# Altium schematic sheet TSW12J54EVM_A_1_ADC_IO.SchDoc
size 431 x 279 mm; Date: Not shown in title block; ApprovedBy: Not shown in title block; CheckedBy: Not shown in title block; Author: Not shown in title block; CompanyName: Not shown in title block; Engineer: Not shown in title block; Organization: Not shown in title block; Address1: Not shown in title block; Address2: Not shown in title block; Address3: Not shown in title block; Address4: Not shown in title block; DocumentNumber: 1; Revision: Use project parameter SCH_Rev; SheetNumber: 1; SheetTotal: 8; PageSetup: Record=PageOptions¦CenterHorizontal=True¦CenterVertical=True¦PrintScale=1.32¦XCorrection=1.00¦YCorrection=1.00¦PrintKind=0¦BorderSize=5000000¦LeftOffset=0¦BottomOffset=0¦Orientation=2¦PaperLength=1000¦PaperWidth=1000¦Scale=100¦PaperSource=15¦PrintQuality=600¦MediaType=1¦DitherType=10¦PaperKind=Letter¦PrintScaleMode=1
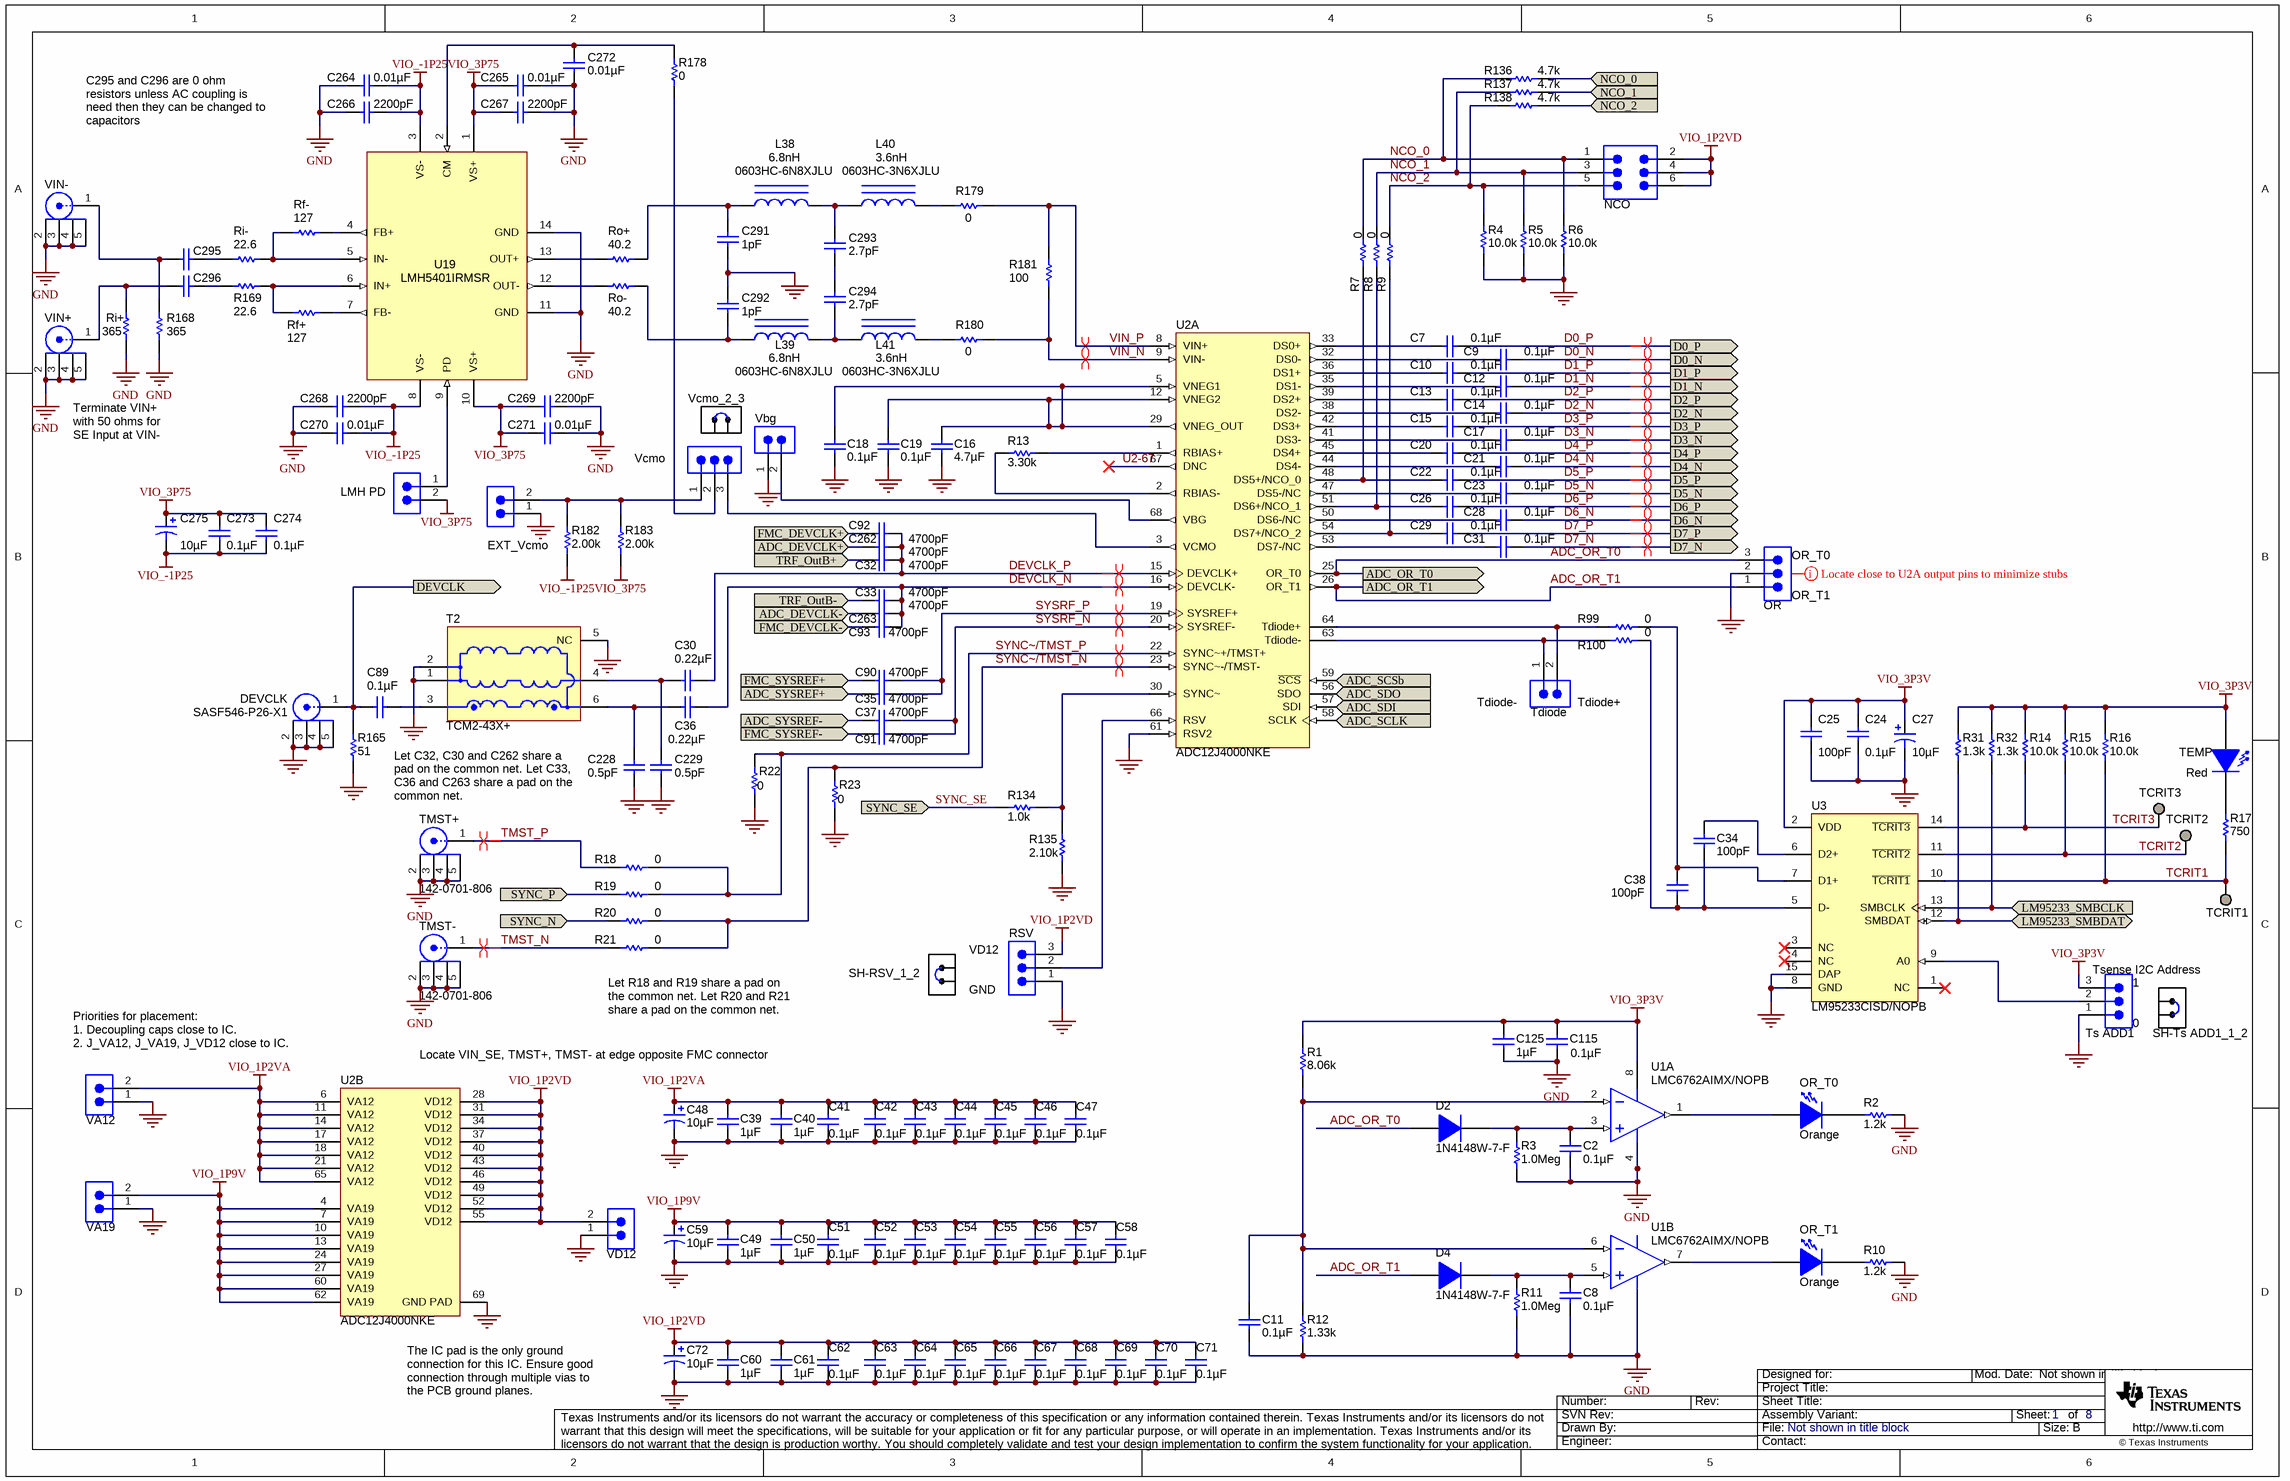
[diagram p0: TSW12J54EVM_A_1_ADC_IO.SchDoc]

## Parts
C2  ValueDisplayed: 0.1µF  [0402L]  (hidden comment: GRM155R71A104KA01D)
C7  ValueDisplayed: 0.1µF  [0201]  (hidden comment: C0603X5R0J104K)
C8  ValueDisplayed: 0.1µF  [0402L]  (hidden comment: GRM155R71A104KA01D)
C9  ValueDisplayed: 0.1µF  [0201]  (hidden comment: C0603X5R0J104K)
C10  ValueDisplayed: 0.1µF  [0201]  (hidden comment: C0603X5R0J104K)
C11  ValueDisplayed: 0.1µF  [0402L]  (hidden comment: GRM155R71A104KA01D)
C12  ValueDisplayed: 0.1µF  [0201]  (hidden comment: C0603X5R0J104K)
C13  ValueDisplayed: 0.1µF  [0201]  (hidden comment: C0603X5R0J104K)
C14  ValueDisplayed: 0.1µF  [0201]  (hidden comment: C0603X5R0J104K)
C15  ValueDisplayed: 0.1µF  [0201]  (hidden comment: C0603X5R0J104K)
C16  ValueDisplayed: 4.7µF  [0402L]  (hidden comment: C1005X5R0J475M050BC)
C17  ValueDisplayed: 0.1µF  [0201]  (hidden comment: C0603X5R0J104K)
C18  ValueDisplayed: 0.1µF  [0402L]  (hidden comment: C1005X5R1A104K)
C19  ValueDisplayed: 0.1µF  [0402L]  (hidden comment: C1005X5R1A104K)
C20  ValueDisplayed: 0.1µF  [0201]  (hidden comment: C0603X5R0J104K)
C21  ValueDisplayed: 0.1µF  [0201]  (hidden comment: C0603X5R0J104K)
C22  ValueDisplayed: 0.1µF  [0201]  (hidden comment: C0603X5R0J104K)
C23  ValueDisplayed: 0.1µF  [0201]  (hidden comment: C0603X5R0J104K)
C24  ValueDisplayed: 0.1µF  [0603L]  (hidden comment: 0603YC104JAT2A)
C25  ValueDisplayed: 100pF  [0603L]  (hidden comment: 06035A101JAT2A)
C26  ValueDisplayed: 0.1µF  [0201]  (hidden comment: C0603X5R0J104K)
C27  ValueDisplayed: 10µF  [3528-21]  (hidden comment: 293D106X0010B2TE3)
C28  ValueDisplayed: 0.1µF  [0201]  (hidden comment: C0603X5R0J104K)
C29  ValueDisplayed: 0.1µF  [0201]  (hidden comment: C0603X5R0J104K)
C30  ValueDisplayed: 0.22µF  [0201]  (hidden comment: C0603X5R0J224M)
C31  ValueDisplayed: 0.1µF  [0201]  (hidden comment: C0603X5R0J104K)
C32  ValueDisplayed: 4700pF  [0201]  (hidden comment: GRM033R61A472KA01D)
C33  ValueDisplayed: 4700pF  [0201]  (hidden comment: GRM033R61A472KA01D)
C34  ValueDisplayed: 100pF  [0603L]  (hidden comment: 06035A101JAT2A)
C35  ValueDisplayed: 4700pF  [0201]  (hidden comment: GRM033R61A472KA01D)
C36  ValueDisplayed: 0.22µF  [0201]  (hidden comment: C0603X5R0J224M)
C37  ValueDisplayed: 4700pF  [0201]  (hidden comment: GRM033R61A472KA01D)
C38  ValueDisplayed: 100pF  [0603L]  (hidden comment: 06035A101JAT2A)
C39  ValueDisplayed: 1µF  [0603L]  (hidden comment: C1608X5R1A105K)
C40  ValueDisplayed: 1µF  [0603L]  (hidden comment: C1608X5R1A105K)
C41  ValueDisplayed: 0.1µF  [0201]  (hidden comment: C0603X5R0J104K)
C42  ValueDisplayed: 0.1µF  [0201]  (hidden comment: C0603X5R0J104K)
C43  ValueDisplayed: 0.1µF  [0201]  (hidden comment: C0603X5R0J104K)
C44  ValueDisplayed: 0.1µF  [0201]  (hidden comment: C0603X5R0J104K)
C45  ValueDisplayed: 0.1µF  [0201]  (hidden comment: C0603X5R0J104K)
C46  ValueDisplayed: 0.1µF  [0201]  (hidden comment: C0603X5R0J104K)
C47  ValueDisplayed: 0.1µF  [0201]  (hidden comment: C0603X5R0J104K)
C48  ValueDisplayed: 10µF  [3528-21]  (hidden comment: 293D106X0010B2TE3)
C49  ValueDisplayed: 1µF  [0603L]  (hidden comment: C1608X5R1A105K)
C50  ValueDisplayed: 1µF  [0603L]  (hidden comment: C1608X5R1A105K)
C51  ValueDisplayed: 0.1µF  [0201]  (hidden comment: C0603X5R0J104K)
C52  ValueDisplayed: 0.1µF  [0201]  (hidden comment: C0603X5R0J104K)
C53  ValueDisplayed: 0.1µF  [0201]  (hidden comment: C0603X5R0J104K)
C54  ValueDisplayed: 0.1µF  [0201]  (hidden comment: C0603X5R0J104K)
C55  ValueDisplayed: 0.1µF  [0201]  (hidden comment: C0603X5R0J104K)
C56  ValueDisplayed: 0.1µF  [0201]  (hidden comment: C0603X5R0J104K)
C57  ValueDisplayed: 0.1µF  [0201]  (hidden comment: C0603X5R0J104K)
C58  ValueDisplayed: 0.1µF  [0201]  (hidden comment: C0603X5R0J104K)
C59  ValueDisplayed: 10µF  [3528-21]  (hidden comment: 293D106X0010B2TE3)
C60  ValueDisplayed: 1µF  [0603L]  (hidden comment: C1608X5R1A105K)
C61  ValueDisplayed: 1µF  [0603L]  (hidden comment: C1608X5R1A105K)
C62  ValueDisplayed: 0.1µF  [0201]  (hidden comment: C0603X5R0J104K)
C63  ValueDisplayed: 0.1µF  [0201]  (hidden comment: C0603X5R0J104K)
C64  ValueDisplayed: 0.1µF  [0201]  (hidden comment: C0603X5R0J104K)
C65  ValueDisplayed: 0.1µF  [0201]  (hidden comment: C0603X5R0J104K)
C66  ValueDisplayed: 0.1µF  [0201]  (hidden comment: C0603X5R0J104K)
C67  ValueDisplayed: 0.1µF  [0201]  (hidden comment: C0603X5R0J104K)
C68  ValueDisplayed: 0.1µF  [0201]  (hidden comment: C0603X5R0J104K)
C69  ValueDisplayed: 0.1µF  [0201]  (hidden comment: C0603X5R0J104K)
C70  ValueDisplayed: 0.1µF  [0201]  (hidden comment: C0603X5R0J104K)
C71  ValueDisplayed: 0.1µF  [0201]  (hidden comment: C0603X5R0J104K)
C72  ValueDisplayed: 10µF  [3528-21]  (hidden comment: 293D106X0010B2TE3)
C89  ValueDisplayed: 0.1µF  [0402L]  (hidden comment: C1005X5R1A104K)
C90  ValueDisplayed: 4700pF  [0201]  (hidden comment: GRM033R61A472KA01D)
C91  ValueDisplayed: 4700pF  [0201]  (hidden comment: GRM033R61A472KA01D)
C92  ValueDisplayed: 4700pF  [0201]  (hidden comment: GRM033R61A472KA01D)
C93  ValueDisplayed: 4700pF  [0201]  (hidden comment: GRM033R61A472KA01D)
C115  ValueDisplayed: 0.1µF  [0603L]  (hidden comment: 0603YC104JAT2A)
C125  ValueDisplayed: 1µF  [0603L]  (hidden comment: C1608X5R1A105K)
C228  ValueDisplayed: 0.5pF  [0402L]  (hidden comment: 500R07S0R5BV4T)
C229  ValueDisplayed: 0.5pF  [0402L]  (hidden comment: 500R07S0R5BV4T)
C262  ValueDisplayed: 4700pF  [0201]  (hidden comment: GRM033R61A472KA01D)
C263  ValueDisplayed: 4700pF  [0201]  (hidden comment: GRM033R61A472KA01D)
C264  ValueDisplayed: 0.01µF  [0306]  (hidden comment: LLL185R71E103MA01L)
C265  ValueDisplayed: 0.01µF  [0306]  (hidden comment: LLL185R71E103MA01L)
C266  ValueDisplayed: 2200pF  [0306]  (hidden comment: LLL185R71H222MA01L)
C267  ValueDisplayed: 2200pF  [0306]  (hidden comment: LLL185R71H222MA01L)
C268  ValueDisplayed: 2200pF  [0306]  (hidden comment: LLL185R71H222MA01L)
C269  ValueDisplayed: 2200pF  [0306]  (hidden comment: LLL185R71H222MA01L)
C270  ValueDisplayed: 0.01µF  [0306]  (hidden comment: LLL185R71E103MA01L)
C271  ValueDisplayed: 0.01µF  [0306]  (hidden comment: LLL185R71E103MA01L)
C272  ValueDisplayed: 0.01µF  [0402L]  (hidden comment: C1005X7R1E103K)
C273  ValueDisplayed: 0.1µF  [0402L]  (hidden comment: C1005X5R1A104K)
C274  ValueDisplayed: 0.1µF  [0402L]  (hidden comment: C1005X5R1A104K)
C275  ValueDisplayed: 10µF  [3216-18]  (hidden comment: TPSA106K010R0900)
C291  ValueDisplayed: 1pF  [0402L]  (hidden comment: GRM1555C1H1R0CA01D)
C292  ValueDisplayed: 1pF  [0402L]  (hidden comment: GRM1555C1H1R0CA01D)
C293  ValueDisplayed: 2.7pF  [0402L]  (hidden comment: GRM1555C1H2R7CA01D)
C294  ValueDisplayed: 2.7pF  [0402L]  (hidden comment: GRM1555C1H2R7CA01D)
C295  Used in BOM report  [0402L]  (value not drawn)
C296  Used in BOM report  [0402L]  (value not drawn)
D2  1N4148W-7-F  [SOD-123]
D4  1N4148W-7-F  [SOD-123]
DEVCLK  SASF546-P26-X1  [CONN_LTI_SASF546-P26-X1]
EXT_Vcmo  TSW-102-07-G-S  [TSW-102-07-G-S]  (value not drawn)
L38  0603HC-6N8XJLU  ValueDisplayed: 6.8nH  [0603HC]
L39  0603HC-6N8XJLU  ValueDisplayed: 6.8nH  [0603HC]
L40  0603HC-3N6XJLU  ValueDisplayed: 3.6nH  [0603HC]
L41  0603HC-3N6XJLU  ValueDisplayed: 3.6nH  [0603HC]
LMH_PD  TSW-102-07-G-S  [TSW-102-07-G-S]  (value not drawn)
NCO  TSW-103-07-G-D  [TSW-103-07-G-D]  (value not drawn)
OR  TSW-103-07-G-S  [TSW-103-07-G-S]  (value not drawn)
OR_T0  value Orange  [LED_LTST-C190]  (hidden comment: LTST-C190KFKT)
OR_T1  value Orange  [LED_LTST-C190]  (hidden comment: LTST-C190KFKT)
R1  value 8.06k  [0402L]  (hidden comment: CRCW04028K06FKED)
R2  value 1.2k  [0402L]  (hidden comment: CRCW04021K20JNED)
R3  value 1.0Meg  [0402L]  (hidden comment: CRCW04021M00JNED)
R4  value 10.0k  [0603L]  (hidden comment: CRCW060310K0FKEA)
R5  value 10.0k  [0603L]  (hidden comment: CRCW060310K0FKEA)
R6  value 10.0k  [0603L]  (hidden comment: CRCW060310K0FKEA)
R7  value 0  [0201]  (hidden comment: ERJ-1GE0R00C)
R8  value 0  [0201]  (hidden comment: ERJ-1GE0R00C)
R9  value 0  [0201]  (hidden comment: ERJ-1GE0R00C)
R10  value 1.2k  [0402L]  (hidden comment: CRCW04021K20JNED)
R11  value 1.0Meg  [0402L]  (hidden comment: CRCW04021M00JNED)
R12  value 1.33k  [0402L]  (hidden comment: CRCW04021K33FKED)
R13  value 3.30k  [0603L]  (hidden comment: RG1608P-332-B-T5)
R14  value 10.0k  [0603L]  (hidden comment: CRCW060310K0FKEA)
R15  value 10.0k  [0603L]  (hidden comment: CRCW060310K0FKEA)
R16  value 10.0k  [0603L]  (hidden comment: CRCW060310K0FKEA)
R17  value 750  [0603L]  (hidden comment: RC0603JR-07750RL)
R18  value 0  [0201]  (hidden comment: ERJ-1GE0R00C)
R19  value 0  [0201]  (hidden comment: ERJ-1GE0R00C)
R20  value 0  [0201]  (hidden comment: ERJ-1GE0R00C)
R21  value 0  [0201]  (hidden comment: ERJ-1GE0R00C)
R22  value 0  [0201]  (hidden comment: ERJ-1GE0R00C)
R23  value 0  [0201]  (hidden comment: ERJ-1GE0R00C)
R31  value 1.3k  [0603L]  (hidden comment: RC0603JR-071K3L)
R32  value 1.3k  [0603L]  (hidden comment: RC0603JR-071K3L)
R99  value 0  [0603L]  (hidden comment: ERJ-3GEY0R00V)
R100  value 0  [0603L]  (hidden comment: ERJ-3GEY0R00V)
R134  value 1.0k  [0603L]  (hidden comment: RC0603JR-071KL)
R135  value 2.10k  [0603L]  (hidden comment: CRCW06032K10FKEA)
R136  value 4.7k  [0603L]  (hidden comment: CRCW06034K70JNEA)
R137  value 4.7k  [0603L]  (hidden comment: CRCW06034K70JNEA)
R138  value 4.7k  [0603L]  (hidden comment: CRCW06034K70JNEA)
R165  value 51  [0402L]  (hidden comment: CRCW040251R0JNED)
R168  ValueDisplayed: 365  [0402L]  (hidden comment: CRCW0402365RFKED)
R169  ValueDisplayed: 22.6  [0402L]  (hidden comment: CRCW040222R6FKED)
R178  value 0  [0402L]  (hidden comment: CRCW04020000Z0ED)
R179  value 0  [0402L]  (hidden comment: CRCW04020000Z0ED)
R180  value 0  [0402L]  (hidden comment: CRCW04020000Z0ED)
R181  value 100  [0402L]  (hidden comment: CRCW0402100RFKED)
R182  ValueDisplayed: 2.00k  [0402L]  (hidden comment: CRCW04022K00FKED)
R183  ValueDisplayed: 2.00k  [0402L]  (hidden comment: CRCW04022K00FKED)
Rf+  ValueDisplayed: 127  [0402L]  (hidden comment: CRCW0402127RFKED)
Rf-  ValueDisplayed: 127  [0402L]  (hidden comment: CRCW0402127RFKED)
Ri+  ValueDisplayed: 365  [0402L]  (hidden comment: CRCW0402365RFKED)
Ri-  ValueDisplayed: 22.6  [0402L]  (hidden comment: CRCW040222R6FKED)
Ro+  value 40.2  [0402L]  (hidden comment: CRCW040240R2FKED)
Ro-  value 40.2  [0402L]  (hidden comment: CRCW040240R2FKED)
RSV  TSW-103-07-G-S  [TSW-103-07-G-S]  (value not drawn)
SH-RSV_1_2  969102-0000-DA  [SNT-100-BK-G]  (value not drawn)
SH-Ts_ADD1_1_2  969102-0000-DA  [SNT-100-BK-G]  (value not drawn)
T2  TCM2-43X+  [Mini-Circuits-DB1627]
TCRIT1  TESTPOINT  [TESTPOINT]  (value not drawn)  (no BOM)
TCRIT2  TESTPOINT  [TESTPOINT]  (value not drawn)  (no BOM)
TCRIT3  TESTPOINT  [TESTPOINT]  (value not drawn)  (no BOM)
Tdiode  TSW-102-07-G-S  [TSW-102-07-G-S]  (value not drawn)
TEMP  value Red  [LED_LTST-C170]  (hidden comment: LTST-C170KRKT)
TMST+  142-0701-806  [Johnson_142-0701-80x]
TMST-  142-0701-806  [Johnson_142-0701-80x]
Ts_ADD1  TSW-103-07-G-S  [TSW-103-07-G-S]  (value not drawn)
U1  LMC6762AIMX/NOPB  [M08A_L]  (parts A,B of 2)
U2  ADC12J4000NKE  [RLY0068A]  (parts A,B of 2)
U3  LM95233CISD/NOPB  [SDA14B]
U19  LMH5401IRMSR  [RMS0014A]
VA12  TSW-102-07-G-S  [TSW-102-07-G-S]  (value not drawn)
VA19  TSW-102-07-G-S  [TSW-102-07-G-S]  (value not drawn)
Vbg  TSW-102-07-G-S  [TSW-102-07-G-S]  (value not drawn)
Vcmo  TSW-103-07-G-S  [TSW-103-07-G-S]  (value not drawn)
Vcmo_2_3  969102-0000-DA  [SNT-100-BK-G]  (value not drawn)
VD12  TSW-102-07-G-S  [TSW-102-07-G-S]  (value not drawn)
VIN+  142-0701-231  [Johnson_142-0701-231]  (value not drawn)
VIN-  142-0701-231  [Johnson_142-0701-231]  (value not drawn)

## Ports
ADC_DEVCLK+ (in), ADC_DEVCLK- (in), ADC_OR_T0 (out), ADC_OR_T1 (out), ADC_SCLK (in), ADC_SCSb (in), ADC_SDI (in), ADC_SDO (out), ADC_SYSREF+, ADC_SYSREF-, D0_N (out), D0_P (out), D1_N (out), D1_P (out), D2_N (out), D2_P (out), D3_N (out), D3_P (out), D4_N (out), D4_P (out), D5_N (out), D5_P (out), D6_N (out), D6_P (out), D7_N (out), D7_P (out), DEVCLK (out), FMC_DEVCLK+ (in), FMC_DEVCLK- (in), FMC_SYSREF+, FMC_SYSREF-, LM95233_SMBCLK (in), LM95233_SMBDAT (bidir), NCO_0 (in), NCO_1 (in), NCO_2 (in), SYNC_N (in), SYNC_P (in), SYNC_SE (in), TRF_OutB+ (in), TRF_OutB- (in)

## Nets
GND: C2.2 C8.2 C11.2 C16.1 C18.1 C19.1 C24.2 C25.2 C27.2(-) C39.2 C40.2 C41.1 C42.1 C43.1 C44.1 C45.1 C46.1 C47.1 C48.2(-) C49.2 C50.2 C51.1 C52.1 C53.1 C54.1 C55.1 C56.1 C57.1 C58.1 C59.2(-) C60.2 C61.2 C62.1 C63.1 C64.1 C65.1 C66.1 C67.1 C68.1 C69.1 C70.1 C71.1 C72.2(-) C115.2 C125.2 C228.2 C229.2 C264.1 C265.2 C266.2 C267.1 C268.2 C269.1 C270.1 C271.2 C272.1 C291.2 C292.1 DEVCLK.2 DEVCLK.3 DEVCLK.4 DEVCLK.5 EXT_Vcmo.1 OR.2 R2.2 R3.1 R4.1 R5.1 R6.1 R10.2 R11.1 R12.1 R22.2 R23.2 R135.1 R165.1 R168.1 Ri+.1 RSV.1 T2.1 T2.2 T2.5(NC) TMST+.2 TMST+.3 TMST+.4 TMST+.5 TMST-.2 TMST-.3 TMST-.4 TMST-.5 Ts_ADD1.1 U1.4(V-) U2.61(RSV2) U2.69(GND_PAD) U3.8(GND) U3.15(DAP) U19.11(GND) U19.14(GND) VA12.1 VA19.1 Vbg.1 VD12.1 VIN+.2 VIN+.3 VIN+.4 VIN+.5 VIN-.2 VIN-.3 VIN-.4 VIN-.5
VIO_1P2VA: C39.1 C40.1 C41.2 C42.2 C43.2 C44.2 C45.2 C46.2 C47.2 C48.1(+) U2.6(VA12) U2.11(VA12) U2.14(VA12) U2.17(VA12) U2.18(VA12) U2.21(VA12) U2.65(VA12) VA12.2
VIO_1P2VD: C60.1 C61.1 C62.2 C63.2 C64.2 C65.2 C66.2 C67.2 C68.2 C69.2 C70.2 C71.2 C72.1(+) NCO.2 NCO.4 NCO.6 RSV.3 U2.28(VD12) U2.31(VD12) U2.34(VD12) U2.37(VD12) U2.40(VD12) U2.43(VD12) U2.46(VD12) U2.49(VD12) U2.52(VD12) U2.55(VD12) VD12.2
VIO_1P9V: C49.1 C50.1 C51.2 C52.2 C53.2 C54.2 C55.2 C56.2 C57.2 C58.2 C59.1(+) U2.4(VA19) U2.7(VA19) U2.10(VA19) U2.13(VA19) U2.24(VA19) U2.27(VA19) U2.60(VA19) U2.62(VA19) VA19.2
VIO_3P3V: C24.1 C25.1 C27.1(+) C115.1 C125.1 R1.2 R14.2 R15.2 R16.2 R31.2 R32.2 TEMP.1(A) Ts_ADD1.3 U1.8(V+) U3.2(VDD)
VIO_3P75: C265.1 C267.2 C269.2 C271.1 C273.1 C274.1 C275.1(+) LMH_PD.2 R183.1 U19.1(VS+) U19.10(VS+)
VIO_-1P25: C264.2 C266.1 C268.1 C270.2 C273.2 C274.2 C275.2(-) R182.1 U19.3(VS-) U19.8(VS-)
ADC_DEVCLK+: C262.2 ; port ADC_DEVCLK+
ADC_DEVCLK-: C263.2 ; port ADC_DEVCLK-
ADC_OR_T0: D2.2(A) OR.3 U2.25(OR_T0) ; port ADC_OR_T0
ADC_OR_T1: D4.2(A) OR.1 U2.26(OR_T1) ; port ADC_OR_T1
ADC_SCLK: U2.58(SCLK) ; port ADC_SCLK
ADC_SCSb: U2.59(~{SCS}) ; port ADC_SCSb
ADC_SDI: U2.57(SDI) ; port ADC_SDI
ADC_SDO: U2.56(SDO) ; port ADC_SDO
ADC_SYSREF+: C35.2 ; port ADC_SYSREF+
ADC_SYSREF-: C37.2 ; port ADC_SYSREF-
D0_N: C9.1 ; port D0_N
D0_P: C7.1 ; port D0_P
D1_N: C12.1 ; port D1_N
D1_P: C10.1 ; port D1_P
D2_N: C14.1 ; port D2_N
D2_P: C13.1 ; port D2_P
D3_N: C17.1 ; port D3_N
D3_P: C15.1 ; port D3_P
D4_N: C21.1 ; port D4_N
D4_P: C20.1 ; port D4_P
D5_N: C23.1 ; port D5_N
D5_P: C22.1 ; port D5_P
D6_N: C28.1 ; port D6_N
D6_P: C26.1 ; port D6_P
D7_N: C31.1 ; port D7_N
D7_P: C29.1 ; port D7_P
DEVCLK: C89.1 DEVCLK.1 R165.2 ; port DEVCLK
DEVCLK_N: C33.1 C36.1 C93.1 C263.1 U2.16(DEVCLK-)
DEVCLK_P: C30.1 C32.1 C92.1 C262.1 U2.15(DEVCLK+)
FMC_DEVCLK+: C92.2 ; port FMC_DEVCLK+
FMC_DEVCLK-: C93.2 ; port FMC_DEVCLK-
FMC_SYSREF+: C90.2 ; port FMC_SYSREF+
FMC_SYSREF-: C91.2 ; port FMC_SYSREF-
LM95233_SMBCLK: R32.1 U3.13(SMBCLK) ; port LM95233_SMBCLK
LM95233_SMBDAT: R31.1 U3.12(SMBDAT) ; port LM95233_SMBDAT
NCO_0: NCO.1 R6.2 R7.1 R136.1
NCO_0: R136.2 ; port NCO_0  [a separate net that carries the same name]
NCO_1: NCO.3 R5.2 R8.1 R137.1
NCO_1: R137.2 ; port NCO_1  [a separate net that carries the same name]
NCO_2: NCO.5 R4.2 R9.1 R138.1
NCO_2: R138.2 ; port NCO_2  [a separate net that carries the same name]
SYNC_N: R20.2 ; port SYNC_N
SYNC_P: R19.2 ; port SYNC_P
SYNC_SE: R134.1 ; port SYNC_SE
SYNC~/TMST_N: R20.1 R21.1 R23.1 U2.23(SYNC~-/TMST-)
SYNC~/TMST_P: R18.1 R19.1 R22.1 U2.22(SYNC~+/TMST+)
SYSRF_N: C37.1 C91.1 U2.20(SYSREF-)
SYSRF_P: C35.1 C90.1 U2.19(SYSREF+)
TCRIT1: R16.1 R17.1 TCRIT1.1 U3.10(~{TCRIT1})
TCRIT2: R15.1 TCRIT2.1 U3.11(~{TCRIT2})
TCRIT3: R14.1 TCRIT3.1 U3.14(~{TCRIT3})
TMST_N: R21.2 TMST-.1
TMST_P: R18.2 TMST+.1
TRF_OutB+: C32.2 ; port TRF_OutB+
TRF_OutB-: C33.2 ; port TRF_OutB-
U2-67: U2.67(DNC)
VIN_N: R180.2 R181.1 U2.9(VIN-)
VIN_P: R179.2 R181.2 U2.8(VIN+)
NetC2_1: C2.1 D2.1(K) R3.2 U1.3(INA+)
NetC7_2: C7.2 U2.33(DS0+)
NetC8_1: C8.1 D4.1(K) R11.2 U1.5(INB+)
NetC9_2: C9.2 U2.32(DS0-)
NetC10_2: C10.2 U2.36(DS1+)
NetC11_1: C11.1 R1.1 R12.2 U1.2(INA-) U1.6(INB-)
NetC12_2: C12.2 U2.35(DS1-)
NetC13_2: C13.2 U2.39(DS2+)
NetC14_2: C14.2 U2.38(DS2-)
NetC15_2: C15.2 U2.42(DS3+)
NetC16_2: C16.2 C18.2 C19.2 U2.5(VNEG1) U2.12(VNEG2) U2.29(VNEG_OUT)
NetC17_2: C17.2 U2.41(DS3-)
NetC20_2: C20.2 U2.45(DS4+)
NetC21_2: C21.2 U2.44(DS4-)
NetC22_2: C22.2 R7.2 U2.48(DS5+/NCO_0)
NetC23_2: C23.2 U2.47(DS5-/NC)
NetC26_2: C26.2 R8.2 U2.51(DS6+/NCO_1)
NetC28_2: C28.2 U2.50(DS6-/NC)
NetC29_2: C29.2 R9.2 U2.54(DS7+/NCO_2)
NetC30_2: C30.2 C229.1 T2.4
NetC31_2: C31.2 U2.53(DS7-/NC)
NetC34_1: C34.1 U3.6(D2+)
NetC34_2: C34.2 C38.2 R100.2 U3.5(D-)
NetC36_2: C36.2 C228.1 T2.6
NetC38_1: C38.1 R99.2 U3.7(D1+)
NetC89_2: C89.2 T2.3
NetC272_2: C272.2 R178.2 U19.2(CM)
NetC291_1: C291.1 L38.1 Ro+.2
NetC292_2: C292.2 L39.1 Ro-.2
NetC293_1: C293.1 L38.2 L40.1
NetC293_2: C293.2 C294.1
NetC294_2: C294.2 L39.2 L41.1
NetC295_1: C295.1 Ri-.1
NetC295_2: C295.2 R168.2 VIN-.1
NetC296_1: C296.1 R169.2
NetC296_2: C296.2 Ri+.2 VIN+.1
NetEXT_Vcmo_2: EXT_Vcmo.2 R182.2 R183.2 Vcmo.1
NetL40_2: L40.2 R179.1
NetL41_2: L41.2 R180.1
NetLMH_PD_1: LMH_PD.1 U19.9(PD)
NetOR_T0_1: OR_T0.1(A) U1.1(OUTA)
NetOR_T0_2: OR_T0.2(K) R2.1
NetOR_T1_1: OR_T1.1(A) U1.7(OUTB)
NetOR_T1_2: OR_T1.2(K) R10.1
NetR13_1: R13.1 U2.2(RBIAS-)
NetR13_2: R13.2 U2.1(RBIAS+)
NetR17_2: R17.2 TEMP.2(K)
NetR99_1: R99.1 Tdiode.2 U2.64(Tdiode+)
NetR100_1: R100.1 Tdiode.1 U2.63(Tdiode-)
NetR134_2: R134.2 R135.2 U2.30(SYNC~)
NetR169_1: R169.1 Rf+.2 U19.6(IN+)
NetR178_1: R178.1 Vcmo.2
NetRf+_1: Rf+.1 U19.7(FB-)
NetRf-_1: Rf-.1 U19.4(FB+)
NetRf-_2: Rf-.2 Ri-.2 U19.5(IN-)
NetRo+_1: Ro+.1 U19.13(OUT+)
NetRo-_1: Ro-.1 U19.12(OUT-)
NetRSV_2: RSV.2 U2.66(RSV)
NetTs_ADD1_2: Ts_ADD1.2 U3.9(A0)
NetU2_3: U2.3(VCMO) Vcmo.3
NetU2_68: U2.68(VBG) Vbg.2

Not connected (* = marked no-connect by the designer): U3 1(NC)* 3(NC)* 4(NC)*

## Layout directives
differential pair: D0_N, D0_P, D1_N, D1_P, D2_N, D2_P, D3_N, D3_P, D4_N, D4_P, D5_N, D5_P, D6_N, D6_P, D7_N, D7_P, DEVCLK_N, DEVCLK_P, SYNC~/TMST_N, SYNC~/TMST_P, SYSRF_N, SYSRF_P, TMST_N, TMST_P, VIN_N, VIN_P
rule Undefined: (no net found under the mark)

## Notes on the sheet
- C295 and C296 are 0 ohm resistors unless AC coupling is need then they can be changed to capacitors
- Terminate VIN+ with 50 ohms for SE Input at VIN-
- (near OR) OR_T0
- (near OR) OR_T1
- (near Tdiode) Tdiode-
- (near Tdiode) Tdiode+
- Let C32, C30 and C262 share a pad on the common net. Let C33, C36 and C263 share a pad on the common net.
- VD12
- (near Ts_ADD1) Tsense I2C Address
- (near R21) Let R18 and R19 share a pad on the common net. Let R20 and R21 share a pad on the common net.
- GND
- (near SH-Ts_ADD1_1_2) 1
- (near SH-Ts_ADD1_1_2) 0
- (near VA12) Priorities for placement:
  1. Decoupling caps close to IC.
  2. J_VA12, J_VA19, J_VD12 close to IC.
- Locate VIN_SE, TMST+, TMST- at edge opposite FMC connector
- (near U2) The IC pad is the only ground connection for this IC. Ensure good connection through multiple vias to the PCB ground planes.

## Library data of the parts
C2 C8 C11 = GRM155R71A104KA01D: CAP, CERM, 0.1uF, 10V, +/-10%, X7R, 0402; Manufacturer: MuRata; Polarized: N; CompType: Capacitor; U/M: EA; Cap_F: 0.0000001; Tolerance_%: 10; TaMin_C: -55; TaMax_C: 125; Cap_Case: 0402
C7 C9 C10 C12-C15 C17 C20-C23 C26 C28 C29 C31 C41-C47 C51-C58 C62-C71 = Capacitor: CAP, CERM, 0.1uF, 6.3V, X5R, 10%, 0201; Manufacturer: TDK; Polarized: N; U/M: EA
C16 = C1005X5R0J475M050BC: CAP, CERM, 4.7uF, 6.3V, +/-20%, X5R, 0402; Manufacturer: TDK; Polarized: N; CompType: Capacitor; U/M: EA; Cap_F: 0.0000047; Tolerance_%: 20; Value1: Unknown; VDC_V: 6.3; TaMin_C: -55; TaMax_C: 85; Cap_Case: 0402
C18 C19 C89 C273 C274 = C1005X5R1A104K: CAP, CERM, 0.1uF, 10V, +/-10%, X5R, 0402; Manufacturer: TDK; Polarized: N; CompType: Capacitor; U/M: EA; Cap_F: 0.0000001; Tolerance_%: 10; ESR_Ohm: 0.0186; Value1: 0.0186 ohm; TaMin_C: -55; TaMax_C: 85; Cap_Case: 0402
C24 C115 = 0603YC104JAT2A: CAP, CERM, 0.1uF, 16V, +/-5%, X7R, 0603; Manufacturer: AVX; Polarized: N; CompType: Capacitor; U/M: EA; Cap_F: 0.0000001; Tolerance_%: 5; ESR_Ohm: 0.039; Value1: 0.039 ohm; VDC_V: 16; TaMin_C: -55; TaMax_C: 125; Cap_Case: 0603
C25 C34 C38 = 06035A101JAT2A: CAP, CERM, 100pF, 50V, +/-5%, C0G/NP0, 0603; Manufacturer: AVX; Polarized: N; CompType: Capacitor; U/M: EA; Cap_F: 0.0000000001; Tolerance_%: 5; ESR_Ohm: 0.119; Value1: 0.119 ohm; VDC_V: 50; TaMin_C: -55; TaMax_C: 125; Cap_Case: 0603
C27 C48 C59 C72 = 293D106X0010B2TE3: CAP, TANT, 10uF, 10V, +/-20%, 2.5 ohm, 3528-21 SMD; Manufacturer: Vishay-Sprague; Polarized: Y; CompType: Capacitor; U/M: EA; Cap_F: 0.00001; Tolerance_%: 20; Value1: 2.5 ohm; VDC_V: 10; ESR_Ohm: 2.5; IRMS_A: 0.18; TaMin_C: -55; TaMax_C: 125; Cap_Case: B
C30 C36 = C0603X5R0J224M: CAP, CERM, 0.22uF, 6.3V, +/-20%, X5R, 0201; Manufacturer: TDK; Polarized: N; CompType: Capacitor; U/M: EA; Cap_F: 0.00000022; Tolerance_%: 20; Value1: Unknown; VDC_V: 6.3; TaMin_C: -55; TaMax_C: 85
C32 C33 C35 C37 C90-C93 C262 C263 = GRM033R61A472KA01D: CAP, CERM, 4700pF, 10V, +/-10%, X5R, 0201; Manufacturer: MuRata; Polarized: N; CompType: Capacitor; U/M: EA; Cap_F: 0.0000000047; Tolerance_%: 10; TaMin_C: -55; TaMax_C: 85
C39 C40 C49 C50 C60 C61 C125 = C1608X5R1A105K: CAP, CERM, 1uF, 10V, +/-10%, X5R, 0603; Manufacturer: TDK; Polarized: N; CompType: Capacitor; U/M: EA; Cap_F: 0.000001; Tolerance_%: 10; ESR_Ohm: 0.0057; Value1: 0.0057 ohm; TaMin_C: -55; TaMax_C: 85; Cap_Case: 0603
C228 C229 = GRM155R71A104KA01D: CAP CER 0.5PF 50V NP0 0402; Manufacturer: Johanson Technology Inc; Polarized: N; CompType: Capacitor; U/M: EA; VDC_V: 50; Cap_Case: 0402
C264 C265 C270 C271 = LLL185R71E103MA01L: CAP, CERM, 0.01uF, 25V, +/-20%, X7R, 0306; Manufacturer: MuRata; Polarized: N; CompType: Capacitor; U/M: EA; Cap_F: 0.00000001; Tolerance_%: 20; Value1: Unknown; VDC_V: 25; TaMin_C: -55; TaMax_C: 125
C266-C269 = LLL185R71H222MA01L: CAP, CERM, 2200pF, 50V, +/-20%, X7R, 0306; Manufacturer: MuRata; Polarized: N; CompType: Capacitor; U/M: EA; Cap_F: 0.0000000022; Tolerance_%: 20; Value1: Unknown; VDC_V: 50; TaMin_C: -55; TaMax_C: 125
C272 = C1005X7R1E103K: CAP, CERM, 0.01uF, 25V, +/-10%, X7R, 0402; Manufacturer: TDK; Cap_Case: 0402; ESR_Ohm: 0.0623; Polarized: N; TaMax_C: 125; TaMin_C: -55; Tolerance_%: 10; VDC_V: 25; Cap_F: 10.0E-9; CompType: Capacitor; Value1: 0.0623 ohm
C275 = TPSA106K010R0900: CAP, TA, 10uF, 10V, +/-10%, 0.9 ohm, SMD; Manufacturer: AVX; Polarized: Y; CompType: Capacitor; U/M: EA; Cap_F: 0.00001; Tolerance_%: 10; Value1: 0.9 ohm; ESR_Ohm: 0.9; IRMS_A: 0.26; TaMin_C: -55; TaMax_C: 125; Cap_Case: A
C291 C292 = GRM1555C1H1R0CA01D: CAP, CERM, 1 pF, 50 V, +/- 5%, C0G/NP0, 0402; Manufacturer: MuRata; Polarized: N; CompType: Capacitor; Value: 1pF; U/M: EA; Cap_F: 0.000000000001; Tolerance_%: 5; Value1: Unknown; VDC_V: 50; Value2: 50V; TaMin_C: -55; TaMax_C: 125; Cap_Case: 0402
C293 C294 = GRM1555C1H2R7CA01D: CAP, CERM, 2.7 pF, 50 V, +/- 5%, C0G/NP0, 0402; Manufacturer: MuRata; Polarized: N; CompType: Capacitor; Value: 2.7pF; U/M: EA; Cap_F: 0.0000000000027; Tolerance_%: 5; Value1: Unknown; VDC_V: 50; Value2: 50V; TaMin_C: -55; TaMax_C: 125; Cap_Case: 0402
C295 C296 = Capacitor: CAP, CERM, xxxF, xxV, [TempCo], xx%, [PackageReference]; Polarized: N; U/M: EA
D2 D4 = 1N4148W-7-F: Diode, Ultrafast, 100V, 0.15A, SOD-123; Manufacturer: Diodes Inc.; U/M: EA; Vf_V: 1.25; Io_A: 0.15; Vr_V: 100; TJmax_C: 150; Value: 1.25V
DEVCLK = SASF546-P26-X1: Connector, SMA,Vertical, Thru hole w/SMT center pin; Manufacturer: Lighthorse Technologies; U/M: EA
EXT_Vcmo LMH_PD Tdiode VA12 VA19 Vbg VD12 = TSW-102-07-G-S: Header, TH, 100mil, 2x1, Gold plated, 230 mil above insulator; Manufacturer: Samtec, Inc.; U/M: EA
L38 L39 = 0603HC-6N8XJLU: Inductor, Wirewound, Ceramic, 6.8 nH, 2.1 A, 0.054 ohm, SMD; Manufacturer: Coilcraft; Value: 6.8nH; Ind_H: 6.8E-9; Imax_A: 2.1; Irms: 2.4A @ 20C rise; DCR_ohm: 0.054; Value2: 2.1A
L40 L41 = 0603HC-3N6XJLU: Inductor, Wirewound, Ceramic, 3.6 nH, 2.3 A, 0.048 ohm, SMD; Manufacturer: Coilcraft; Value: 3.6nH; Ind_H: 3.6E-9; Imax_A: 2.3; Irms: 2.4A @ 20C rise; DCR_ohm: 0.048; Value2: 2.3A
NCO = TSW-103-07-G-D: Header, TH, 100mil, 3x2, Gold plated, 230 mil above insulator; Manufacturer: Samtec, Inc.; Alternate Manufacturer: Any; Alternate PartNumber: Equivalent; U/M: EA
OR RSV Ts_ADD1 Vcmo = TSW-103-07-G-S: Header, TH, 100mil, 3x1, Gold plated, 230 mil above insulator; Manufacturer: Samtec, Inc.; Alternate Manufacturer: Any; Alternate PartNumber: Equivalent; U/M: EA
OR_T0 OR_T1 = LTST-C190KFKT: LED, Orange, SMD; Manufacturer: Lite-On; Vf_V: 2; Value2: 2V; Io_A: 0.02; Power_TotalModule: 0.075; Value1: 0.075W; U/M: EA
R1 = CRCW04028K06FKED: RES, 8.06k ohm, 1%, 0.063W, 0402; Manufacturer: Vishay-Dale; CompType: Resistor; Res_ohm: 8060; Value_Code: 8k06; Tolerance_%: 1; Power_W: 0.063; VDC_V: 50; TempCo: 100 ppm/C; EIA_Code: E96; U/M: EA
R2 R10 = CRCW04021K20JNED: RES, 1.2k ohm, 5%, 0.063W, 0402; Manufacturer: Vishay-Dale; CompType: Resistor; Res_ohm: 1200; Value_Code: 1k20; Tolerance_%: 5; Power_W: 0.063; VDC_V: 50; TempCo: 200 ppm/C; EIA_Code: E24; U/M: EA
R3 R11 = CRCW04021M00JNED: RES, 1.0Meg ohm, 5%, 0.063W, 0402; Manufacturer: Vishay-Dale; CompType: Resistor; Res_ohm: 1000000; Value_Code: 1M00; Tolerance_%: 5; Power_W: 0.063; VDC_V: 50; TempCo: 200 ppm/C; EIA_Code: E24; U/M: EA
R4-R6 R14-R16 = CRCW060310K0FKEA: RES, 10.0k ohm, 1%, 0.1W, 0603; Manufacturer: Vishay-Dale; CompType: Resistor; Res_ohm: 10000; Value_Code: 10k0; Tolerance_%: 1; Power_W: 0.1; VDC_V: 75; TempCo: 100 ppm/C; EIA_Code: E96; U/M: EA
R7-R9 R18-R23 = ERJ-1GE0R00C: RES, 0 ohm, 5%, 0.05W, 0201; Manufacturer: Panasonic; CompType: Resistor; Value_Code: 0000; Tolerance_%: 5; Power_W: 0.05; VDC_V: 15; TempCo: 600 ppm/C; EIA_Code: E24; U/M: EA
R12 = CRCW04021K33FKED: RES, 1.33k ohm, 1%, 0.063W, 0402; Manufacturer: Vishay-Dale; CompType: Resistor; Res_ohm: 1330; Value_Code: 1k33; Tolerance_%: 1; Power_W: 0.063; VDC_V: 50; TempCo: 100 ppm/C; EIA_Code: E96; U/M: EA
R13 = RG1608P-332-B-T5: RES, 3.30k ohm, 0.1%, 0.1W, 0603; Manufacturer: Susumu Co Ltd; CompType: Resistor; Res_ohm: 3300; Value_Code: 3k30; Tolerance_%: 0.1; VDC_V: 75; TempCo: 25 ppm/C; U/M: EA
R17 = RC0603JR-07750RL: RES, 750 ohm, 5%, 0.1W, 0603; Manufacturer: Yageo America; CompType: Resistor; Value_Code: 750R; Tolerance_%: 5; Power_W: 0.1; VDC_V: 50; TempCo: 100 ppm/C; EIA_Code: E24; U/M: EA
R31 R32 = RC0603JR-071K3L: RES, 1.3k ohm, 5%, 0.1W, 0603; Manufacturer: Yageo America; CompType: Resistor; Res_ohm: 1300; Value_Code: 1k30; Tolerance_%: 5; Power_W: 0.1; VDC_V: 50; TempCo: 100 ppm/C; EIA_Code: E24; U/M: EA
R99 R100 = ERJ-3GEY0R00V: RES, 0 ohm, 5%, 0.1W, 0603; Manufacturer: Panasonic; CompType: Resistor; Value_Code: 0000; Tolerance_%: 5; Power_W: 0.1; VDC_V: 50; TempCo: 600 ppm/C; EIA_Code: E24; U/M: EA
R134 = RC0603JR-071KL: RES, 1.0k ohm, 5%, 0.1W, 0603; Manufacturer: Yageo America; CompType: Resistor; Res_ohm: 1000; Value_Code: 1k00; Tolerance_%: 5; Power_W: 0.1; VDC_V: 50; TempCo: 100 ppm/C; EIA_Code: E24; U/M: EA
R135 = CRCW06032K10FKEA: RES, 2.10k ohm, 1%, 0.1W, 0603; Manufacturer: Vishay-Dale; CompType: Resistor; Res_ohm: 2100; Value_Code: 2k10; Tolerance_%: 1; Power_W: 0.1; VDC_V: 75; TempCo: 100 ppm/C; EIA_Code: E96; U/M: EA
R136-R138 = CRCW06034K70JNEA: RES, 4.7k ohm, 5%, 0.1W, 0603; Manufacturer: Vishay-Dale; CompType: Resistor; Res_ohm: 4700; Value_Code: 4k70; Tolerance_%: 5; Power_W: 0.1; VDC_V: 75; TempCo: 200 ppm/C; EIA_Code: E24; U/M: EA
R165 = CRCW040251R0JNED: RES, 51 ohm, 5%, 0.063W, 0402; Manufacturer: Vishay-Dale; Alternate Manufacturer: Any; Alternate PartNumber: Equivalent; CompType: Resistor; Value_Code: 51R0; Tolerance_%: 5; Power_W: 0.063; VDC_V: 50; TempCo: 200 ppm/C; EIA_Code: E24; U/M: EA
R168 Ri+ = CRCW0402365RFKED: RES, 365, 1%, 0.063 W, 0402; Manufacturer: Vishay-Dale; CompType: Resistor; Value: 365; Value_Code: 365R; Tolerance_%: 1; Power_W: 0.063; Value2: 0.063W; VDC_V: 50; TempCo: 100 ppm/C; EIA_Code: E96; U/M: EA
R169 Ri- = CRCW040222R6FKED: RES, 22.6, 1%, 0.063 W, 0402; Manufacturer: Vishay-Dale; CompType: Resistor; Value: 22.6; Value_Code: 22R6; Tolerance_%: 1; Power_W: 0.063; Value2: 0.063W; VDC_V: 50; TempCo: 100 ppm/C; EIA_Code: E96; U/M: EA
R178-R180 = CRCW04020000Z0ED: RES, 0 ohm, 5%, 0.063W, 0402; Manufacturer: Vishay-Dale; CompType: Resistor; Value_Code: 0000; Tolerance_%: 5; Power_W: 0.063; VDC_V: 50; TempCo: 200 ppm/C; EIA_Code: E24; U/M: EA
R181 = CRCW0402100RFKED: RES, 100 ohm, 1%, 0.063W, 0402; Manufacturer: Vishay-Dale; CompType: Resistor; Value_Code: 100R; Tolerance_%: 1; Power_W: 0.063; VDC_V: 50; TempCo: 100 ppm/C; EIA_Code: E96; U/M: EA
R182 R183 = CRCW04022K00FKED: RES, 2.00 k, 1%, 0.063 W, 0402; Manufacturer: Vishay-Dale; CompType: Resistor; Value: 2.00k; Res_ohm: 2000; Value_Code: 2k00; Tolerance_%: 1; Power_W: 0.063; Value2: 0.063W; VDC_V: 50; TempCo: 100 ppm/C; EIA_Code: E96; U/M: EA
Rf+ Rf- = CRCW0402127RFKED: RES, 127, 1%, 0.063 W, 0402; Manufacturer: Vishay-Dale; CompType: Resistor; Value: 127; Value_Code: 127R; Tolerance_%: 1; Power_W: 0.063; Value2: 0.063W; VDC_V: 50; TempCo: 100 ppm/C; EIA_Code: E96; U/M: EA
Ro+ Ro- = CRCW040240R2FKED: RES, 40.2 ohm, 1%, 0.063W, 0402; Manufacturer: Vishay-Dale; CompType: Resistor; Value_Code: 40R2; Tolerance_%: 1; Power_W: 0.063; VDC_V: 50; TempCo: 100 ppm/C; EIA_Code: E96; U/M: EA
SH-RSV_1_2 SH-Ts_ADD1_1_2 Vcmo_2_3 = 969102-0000-DA: Shunt, 100mil, Gold plated, Black; Manufacturer: 3M; Alternate Manufacturer: Any; Alternate PartNumber: Equivalent; U/M: EA; Value: 1x2; Note: You can "mate" this to a header by matching the designator.  i.e. use SH-J3 for header J3
T2 = TCM2-43X+: Transformer, RF, 50 ohm, 10 to 4000 MHz, SMT; Manufacturer: Minicircuits; SymbolCreator: a0799628; U/M: EA
TCRIT1-TCRIT3 = TESTPOINT: TEST POINT.  No entry in BOM.
TEMP = LTST-C170KRKT: LED, Red, SMD; Manufacturer: Lite-On; Vf_V: 2; Value2: 2V; Io_A: 20; Value1: W; U/M: EA
TMST+ TMST- = 142-0701-806: Connector, SMT, End launch SMA 50 ohm; Manufacturer: Emerson Network Power; Value: 50 Ohm; U/M: EA
U1 = LMC6762AIMX: Dual Micro-Power Rail-to-Rail Input CMOS Comparator with Push-Pull Output, 8-pin Narrow SOIC; Manufacturer: National Semiconductor; PackageTopMarking: NSZXTT*LMC67*62AIM; PowerWise: N
U2 = ADC12X3500RFLQNOPB: ADC12J4000RLY Ultra-Wideband RF Sampling Subsystem, RLY0068A; Alternate Manufacturer: None; Manufacturer: Texas Instruments; SymbolCreator: a0411947; CompType: IC; U/M: EA
U3 = LM95233CISD/NOPB: Dual Remote Diode and Local Temperature Sensor with SMBus Interface and TruTherm Technology, 14-pin LLP, Pb-Free; Manufacturer: National Semiconductor; PackageTopMarking: NS*UZXYTT*95233CI; PowerWise: Y; CompType: Temp Sensor IC
U19 = LMH5401RMS: 8GHz Ultra Wideband Fully Differential Amplifier, RMS0014A; Alternate Manufacturer: None; Manufacturer: Texas Instruments; SymbolCreator: Altium; CompType: IC; U/M: EA
VIN+ VIN- = 142-0701-231: Connector, TH, SMA; Manufacturer: Emerson Network Power; SymbolCreator: X0208326; U/M: EA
